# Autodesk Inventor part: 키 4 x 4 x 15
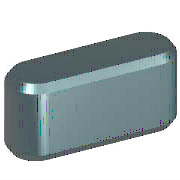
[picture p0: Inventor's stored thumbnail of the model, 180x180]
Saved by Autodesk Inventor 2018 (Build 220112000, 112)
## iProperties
IsCustomPart: 1
Created: 2012-02
Part Number: 키 4 x 4 x 15
Material: 강철, 연강
Description: 키 및 해당 키홈
Document SubType Name: Modeling
Standard: KS B 1311
Designer: test
Standards Organization: KS
Language: ko-KR
Size Designation: 4 x 4 x 10
Categories: <MemberInstance><Categories><Category DisplayName="샤프트 부품" InternalName="7f7aeb1f-a693-4053-b835-cee3144e0d98" Mnemonic="SHFT"><Category DisplayName="키" Interna
Density: 1 g/cm^3
Appearance: 노란색
Author: test
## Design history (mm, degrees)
workplane "Work Plane1"
workplane "Work Plane2"
sketch "스케치1"
  geometry: L1 (2, 2)-(13, 2); L2 (13, -2)-(2, -2); L3 (0, 8.8)-(0, -3.8) reference; L4 (-2, 0)-(12, 0) reference; L5 (15, 0)-(15, 7); A1 r 2 centre (2, 0) between (2, 2) and (2, -2); A2 r 2 centre (13, 0) between (13, -2) and (13, 2)
  constraints: 6 end point, 5 point on circle, 4 tangent, 3 point on line, 2 centre point, 1 horizontal, 1 parallel, 1 perpendicular
  dimensions: "d0" = 2 radius of A1 (= 0.5 x PB); "d13" = 2 radius of A2 (= 0.5 x PB); "d14" = 15 distance between parallel lines of L5 L3 (= NLG)
extrude "본체1" new body sketch "스케치1" taper "d3" = 0 deg; stored distance "d4" = 10
workplane "Work Plane3"
body "Solid1"
chamfer "모따기1" distance "d8" = 0.25 (= PHH); stored, may be unused: second distance "d9" = 0.25 (= PHH), angle "d15" = 45 deg
other parameters: "d1" = -2.5 (= -PNT), "d2" = 1.5 (= PH - PNT), "NLG" = 15 [user parameter; used in 3 equation terms], "PB" = 4 [user parameter; used in 2 equation terms], "PNT" = 2.5 [user parameter; used in 2 equation terms], "PH" = 4 [user parameter; used in 1 equation term], "PHH" = 0.25 [user parameter; used in 2 equation terms], "d10" = 0, "d16" = 0, "d17" = 0, "d18" = 0, "PLB2" = 15 (= NLG) [user parameter], "WDMAX" = 12 [user parameter], "PLB1" = 15 (= NLG) [user parameter], "RR" = 0.08 [user parameter], "PUEB" = 1.8 [user parameter]
